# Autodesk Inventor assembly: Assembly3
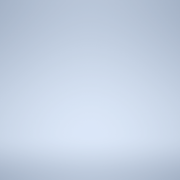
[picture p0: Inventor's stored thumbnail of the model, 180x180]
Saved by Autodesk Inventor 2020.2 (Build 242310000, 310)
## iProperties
Created: 2020-01
Part Number: Assembly3
Document SubType Name: Assembly
Designer: thira
Author: thira
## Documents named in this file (1)
- F:\99.โปรแกรมอัดหน้าจอ\Synergysoft\FRAME\Frame_Generator\Frame\Assembly3.iam
